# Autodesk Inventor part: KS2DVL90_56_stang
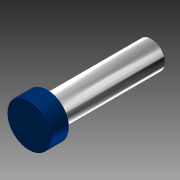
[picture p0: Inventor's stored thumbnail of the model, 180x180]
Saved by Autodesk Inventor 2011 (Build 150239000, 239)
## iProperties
Created: 2010-11
Document SubType Name: Modeling
Designer: TB
Mass: 161.233 g
Surface Area: 236.814 cm^2
Volume: 161.233 cm^3
Density: 1 g/cm^3
Author: TB
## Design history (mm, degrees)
sketch "Sketch2"
  geometry: L1 (-35, -3)-(-35, 3) reference; L2 (-35, -9)-(-35, 9) reference; L3 (-35, 28)-(-288, 28); L4 (-288, 28)-(-288, 0); L5 (-288, 0)-(-35, 0); L6 (-35, 0)-(-35, 28); L7 (-288, 28)-(-249, 28); L8 (-249, 28)-(-249, 45); L9 (-249, 45)-(-288, 45); L10 (-288, 45)-(-288, 28); 1 further point
  constraints: 16 end point, 4 parallel, 2 horizontal, 2 perpendicular, 1 midpoint
  dimensions: "Dia" = 56 diameter of L3 L5; "d3" = 253 distance of L3.start L3.end (computed from Slaglengde, Forlengelse_rør); "StempelDia" = 90 diameter of L9 L5; "StempelLengde" = 39 distance of L8.end L9.end
revolve "Revolution1" sketch "Sketch2" stored, may be unused: angle "d6" = 90 deg
fillet "Fillet1" dims "d7" = 2
sketch "Sketch3"
  geometry: L1 (-288, -43)-(-288, 43) reference; L2 (-288, 0)-(-288.01, 0); L3 (-288, 0)-(-288, 0.01); A1 r 0.01 centre (-288, 0) between (-288, 0.01) and (-288.01, 0); 1 further point
  constraints: 4 end point, 2 point on circle, 1 centre point, 1 midpoint, 1 perpendicular, 1 point on line
  dimensions: "d8" = 0.01 distance of L2.start L2.end; "d9" = 0.01 distance of L2.start L3.end (= d8); "d10" = 0.01 radius of A1 (= d8)
revolve "Revolution2" sketch "Sketch3" stored, may be unused: angle "d11" = 90 deg
body "Solid1"
node "Projected Loop2"
other parameters: "Forlengelse_rør" = 0
